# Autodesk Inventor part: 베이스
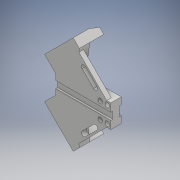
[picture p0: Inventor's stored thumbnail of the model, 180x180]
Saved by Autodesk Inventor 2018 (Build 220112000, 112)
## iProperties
Created: 2020-05
Part Number: 베이스
Material: Generic
Document SubType Name: Modeling
Designer: 1class 18
Density: 1 g/cm^3
Appearance: Default
Mass: 211.712 g
Surface Area: 407.173 cm^2
Volume: 211.712 cm^3
Author: 1class 18
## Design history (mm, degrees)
sketch "스케치2"
  geometry: L1 (0, 84.853)-(-64.853, 20); L2 (-64.853, -20)-(0, -84.853); L3 (0, -84.853)-(49.497, -35.355); L4 (49.497, 35.355)-(0, 84.853); L5 (0, 84.853)-(0, -84.853); L6 (-84.853, 0)-(84.853, 0); L7 (-64.853, 20)-(-64.853, -20); L8 (49.497, -35.355)-(30.147, -16.005); L9 (49.497, 35.355)-(30.147, 16.005); L10 (30.147, 16.005)-(30.147, -16.005); 1 further point
  constraints: 20 end point, 4 parallel, 2 midpoint, 2 perpendicular, 2 vertical, 1 horizontal
  dimensions: "d2" = 120 distance of L6.end L1.start; "d3" = 120 distance of L1.start L6.start; "d7" = 20 distance from line of L7 L6.start; "d9" = 135 deg angle of L10 L3; "d10" = 50 distance between parallel lines of L9 L3; "d11" = 120 distance between parallel lines of L3 L1; "d12" = 50 distance between parallel lines of L4 L8; "d13" = 30.14719 distance between parallel lines of L10 L5; "d14" = 95 distance between parallel lines of L10 L7
extrude "돌출1" new body sketch "스케치2" distance "d15" = 18; taper "d16" = 0 deg
sketch "스케치3"
  geometry: L1 (-49.497, -35.355)-(0, -84.853) reference; L2 (0, 84.853)-(-49.497, 35.355) reference; L3 (0, -84.853)-(64.853, -20) reference; L4 (10.607, -74.246)-(0, -84.853); L5 (0, -84.853)-(-49.497, -35.355); L6 (-49.497, -35.355)-(-38.891, -24.749); L7 (-30.147, -16.005)-(-49.497, -35.355) reference; L8 (-38.891, -24.749)-(10.607, -74.246); L9 (-49.497, 35.355)-(-30.147, 16.005) reference; L10 (-38.891, 24.749)-(-49.497, 35.355); L11 (-49.497, 35.355)-(0, 84.853); L12 (64.853, 20)-(0, 84.853) reference; L13 (10.607, 74.246)-(0, 84.853); L14 (10.607, 74.246)-(-38.891, 24.749); 1 further point
  constraints: 16 end point, 4 collinear, 4 point on line, 2 parallel, 1 perpendicular
  dimensions: "d19" = 15 distance between parallel lines of L1 L8; "d20" = 15 distance between parallel lines of L2 L14
extrude "돌출2" join sketch "스케치3" distance "d21" = 24; taper "d22" = 0 deg
sketch "스케치4"
  geometry: L1 (-30.147, -8)-(64.853, -8); L2 (-30.147, 8)-(64.853, 8); L3 (-30.147, 16.005)-(-30.147, -16.005) reference; L4 (64.853, -20)-(64.853, 20) reference; L5 (64.853, -8)-(64.853, 8); L6 (-30.147, -8)-(-30.147, 8); 1 further point
  constraints: 8 end point, 4 point on line, 2 horizontal, 1 collinear
  dimensions: "d23" = 16 distance between parallel lines of L2 L1; "d24" = 8 distance from line of L1 point (0, 0)
extrude "돌출3" cut sketch "스케치4" distance "d26" = 3.5; taper "d27" = 0 deg
sketch "스케치5"
  geometry: L1 (-30.147, 6)-(64.853, 6); L2 (-30.147, -6)-(64.853, -6); L3 (-30.147, 8)-(-30.147, 16.005) reference; L4 (-30.147, 6)-(-30.147, -6); L5 (-30.147, -16.005)-(-30.147, 16.005) reference; L6 (64.853, 20)-(64.853, -20) reference; L7 (64.853, 6)-(64.853, -6); 1 further point
  constraints: 8 end point, 5 point on line, 2 horizontal
  dimensions: "d28" = 12 distance between parallel lines of L2 L1; "d29" = 6 distance from line of point (0, 0) L2
extrude "돌출4" cut sketch "스케치5" distance "d30" = 3; taper "d31" = 0 deg
sketch "스케치6"
  geometry: L1 (-49.497, -35.355)-(0, -84.853) reference; L2 (10.607, -74.246)-(64.853, -20) reference; L3 (64.853, -8)-(-30.147, -8) reference; L4 (0, -84.853)-(10.607, -74.246) reference; L5 (10.607, -74.246)-(7.071, -49.497); L6 (7.071, -49.497)-(36.569, -20); L7 (36.569, -20)-(64.853, -20); 1 further point
  constraints: 6 end point, 2 parallel, 1 point on line
  dimensions: "d35" = 20 distance between parallel lines of L2 L6; "d36" = 20 distance from line of point (0, 0) L7; "d38" = 126.87 deg angle of L6 L5
extrude "돌출5" cut sketch "스케치6" distance "d39" = 10; taper "d40" = 0 deg
sketch "스케치7"
  geometry: L1 (9.723, -68.059)-(57.782, -20); L2 (64.853, -20)-(10.607, -74.246) reference; L3 (10.607, -74.246)-(7.071, -49.497) reference; L4 (10.607, -74.246)-(9.723, -68.059); L5 (36.569, -20)-(64.853, -20) reference; L6 (64.853, -20)-(57.782, -20); 1 further point
  constraints: 6 end point, 2 point on line, 1 parallel
  dimensions: "d41" = 5 distance between parallel lines of L1 L2
extrude "돌출6" cut sketch "스케치7" distance "d42" = 347.25; taper "d43" = 0 deg
sketch "스케치8"
  geometry: L1 (18.385, -49.497)-(38.184, -29.698); L2 (15.556, -46.669)-(35.355, -26.87); L3 (41.012, -32.527)-(21.213, -52.326); L4 (9.723, -68.059)-(57.782, -20) reference; L5 (0, -84.853)-(10.607, -74.246) reference; L6 (-49.497, -35.355)-(0, -84.853) reference; A1 r 4 centre (18.385, -49.497) between (15.556, -46.669) and (21.213, -52.326); A2 r 4 centre (38.184, -29.698) between (41.012, -32.527) and (35.355, -26.87); 2 further points
  constraints: 8 end point, 4 point on circle, 4 tangent, 2 centre point, 2 parallel, 1 midpoint
  dimensions: "d44" = 12 distance from line of L5 point (28.284, -39.598); "d45" = 38 distance from line of L1.start L6; "d46" = 8 distance between parallel lines of L2 L3; "d48" = 66 distance from line of L1.end L6
extrude "돌출7" cut sketch "스케치8" distance "d49" = 50; taper "d50" = 0 deg
sketch "스케치9"
  geometry: L1 (0, 0)-(0, 42) reference; L2 (0, 42)-(15, 42) reference; L3 (0, 0)-(0, 42) reference; L4 (0, 27)-(5, 42); L5 (0, 27)-(0, 42); L6 (5, 42)-(0, 42); 1 further point
  constraints: 6 end point, 2 point on line, 1 collinear, 1 perpendicular
  dimensions: "d53" = 5 distance of L1.end L4.end; "d54" = 15 distance from line of L4.start L2
extrude "돌출8" cut sketch "스케치9" distance "d55" = 91.25; taper "d56" = 0 deg
sketch "스케치11"
  geometry: L1 (64.853, -6)-(64.853, -20) reference; L2 (64.853, 20)-(64.853, 6) reference; 5 further points
  dimensions: "d66" = 28 distance of point (58.853, 14) point (58.853, -14); "d67" = 14 vertical distance of point (0, 0) point (58.853, -14); "d68" = 28 distance of point (46.853, 14) point (46.853, -14); "d69" = 14 vertical distance of point (0, 0) point (46.853, -14); "d70" = 6 distance from line of L1 point (58.853, -14); "d71" = 6 distance from line of L2 point (58.853, 14); "d72" = 12 distance of point (46.853, -14) point (58.853, -14); "d73" = 12 distance of point (46.853, 14) point (58.853, 14)
hole "구멍1" sketch "스케치11" at (58.853, -14), (58.853, 14), (46.853, 14), (46.853, -14) diameter "d74" = 4.5; stored, may be unused: countersink angle "d78" = 90 deg, drill point angle "d80" = 0 deg; dims "d75" = 6, "d76" = 8, "d77" = 10, "d79" = 18
sketch "스케치12"
  geometry: L1 (10.607, -74.246)-(-38.891, -24.749) reference; L2 (-49.497, -35.355)-(-45.962, -31.82) reference; 2 further points
  constraints: 1 other
  dimensions: "d81" = 5 distance from line of L1 point (-17.678, -53.033); "d82" = 35 distance from line of point (-17.678, -53.033) L2
feature "엠보싱1" sketch "스케치12" dims "d2" = 120, "d83" = 0.5, "d84" = 0
fillet "모깎기1" dims "d85" = 5
fillet "모깎기2" dims "d86" = 5
node "솔리드1"
mirror "미러1"
mirror "미러2"
other parameters: "d8" = 95, "d17" = 15, "d18" = 15
